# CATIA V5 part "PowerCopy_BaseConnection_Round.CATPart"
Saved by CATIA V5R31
Part number: BaseConnection
Bounding box of the stored display mesh (mm): x -5 to 5, y -4.99 to 4.99, z 0 to 15
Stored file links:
  C:\Users\patol451\OneDrive - Linköpings universitet\Nuvarande kurser\Exjobb\LampCATIA\PowerCopy_BaseConnection_Round.CATPart
  C:\Users\patol451\OneDrive - Linköpings universitet\Nuvarande kurser\Exjobb\LampCATIA\LampReference.CATPart
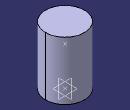
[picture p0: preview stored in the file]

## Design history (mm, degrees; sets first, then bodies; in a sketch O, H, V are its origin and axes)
Parameters
  diameter = 10 mm
Set1 "References"
  Point1 "BaseConnectionPoint_1": (0, 0, 0)
  Point2 "BaseConnectionPoint_2": (0, 0, 10)
Set2 "Placement"
  Point3 "PlacementPoint": (0, 0, 0), relative to Point1
Set3 "Output"
  Point4 "OutputPoint1": (0, 0, 0), relative to Point2
Set4 "GeoSet"
  Line1: type PtPt, FirstPoint Point1, SecondPoint Point2
  Plane1: type Normal, Curve Line1, Ratio 0
  Circle1: type CtrRad, Start 0, End 180, Center Point1, Support Plane1, Radius 5 {= diameter /2}, FirstDirection (1, 0, 0)
  Point5: (0, 0, 5 {= diameter /2}), relative to Point2
  Line2: type PtPt, FirstPoint Point1, SecondPoint Point5
Body1 (main body)
  Rib1: profile Circle1, centre curve Line2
